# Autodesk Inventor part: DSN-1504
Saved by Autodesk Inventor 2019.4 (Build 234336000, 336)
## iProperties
Created: 2020-04
Part Number: DSN-1504
Material: Generic
Document SubType Name: Modeling
Designer: Administrator
Density: 1 g/cm^3
Appearance: Default
Title: DSN-1504
Author: Administrator
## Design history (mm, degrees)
feature "DSN-1504"
body "Solid1"
